(* Logix 5000 project; controller MCM_v18 1756-L63 rev 18.11; software revision 18.01 *)

TASK MainTask (continuous, watchdog 500 ms) : MainProgram

MODULES
   Local : 1756-L63 (ICP 0, rev 18.11)
      MCM : vendor 1 type 0 code 15 (ICP 1, rev 1.1, Output RPI 5 ms)   // ProSoft Technology Modbus communication module for the Control logix platform
END_MODULES

TYPE MCMBlkStat :   // This object is used to store the block transfer statistics for the module.
STRUCT
   Read : INT;   // Total number of read block transfers
   Write : INT;   // Total number of write block transfers
   Parse : INT;   // Total number of blocks parsed
   Event : INT;   // Total number of event blocks received
   Cmd : INT;   // Total number of command blocks received
   Err : INT;   // Total number of block transfer errors
END_STRUCT
END_TYPE

TYPE MCMClockType :   // Allows read/write of clock value between the module and processor
STRUCT
   Read : BOOL;   // Reads current time from the module
   Write : BOOL;   // Writes current time from the module
   Config : MCMDateTime;   // Date and time configuration read or written between the module and processor
END_STRUCT
END_TYPE

TYPE MCMCmd :   // This object is used to contain the attributes to define a master command. An array of these objects is used for each port.
STRUCT
   Enable : INT;   // 0=Disable,1=Continuous,2=Event Command
   IntAddress : INT;   // Module's internal address associated with the command
   PollInt : INT;   // Minimum number of seconds between issuance of command (0-65535 Sec)
   Count : INT;   // Number of registers associated with the command
   Swap : INT;   // Swap code used with command
   Node : INT;   // Node address of the target device on the network
   Func : INT;   // Function code for the command
   DevAddress : INT;   // Address in device associated with the command
END_STRUCT
END_TYPE

TYPE MCMCmdControl :   // Command Control
STRUCT
   TriggerCmdCntrl : BOOL;   // Trigger command control. User application will activate this trigger
   NumberOfCommands : INT;   // Number of commands per block (1 to 6)
   PortNumber : INT;   // MVI56-MCM Port Number of master port (1 or 2)
   CommandIndex : INT[6];   // Stores the command indexes for command control
   CmdsAddedToQueue : INT;   // Number of commands added to queue
   CmdControlBlockID : INT;   // Temporary variable to calculate control block ID
   CmdCntrlPending : BOOL;   // Auxiliary control command - prevents a second request before acknowledgment is received
END_STRUCT
END_TYPE

TYPE MCMCONFIG :   // This object contains the data types that apply to the configuration of the module.
STRUCT
   ModDef : MCMModule;   // Module Defintion
   Port1 : MCMPort;   // Port 1 configuration settings
   Port2 : MCMPort;   // Port 2 configuration settings
   Port1MasterCmd : MCMCmd[325];   // Master commands for Port 1 (ignore if port is configured for slave mode)
   Port2MasterCmd : MCMCmd[325];   // Master commands for Port 2 (ignore if port is configured for slave mode)
END_STRUCT
END_TYPE

TYPE MCMCONTROL :   // Stores control registers used by the processor to request special tasks from the module.
STRUCT
   WarmBoot : BOOL;   // Warm Boot
   ColdBoot : BOOL;   // Cold Boot
   SlaveControl : MCMSlaveControl;
   CmdControl : MCMCmdControl;   // Allows for a disabled command to be sent to a device (MASTER)
   EventCmd : MCMEventCmd;   // Allows a command defined in ladder to be sent to a device (MASTER)
   SlavePollStat : MCMSlavePollStatus;   // Request slave poll status for the port (MASTER).
   Passthru : MCMPassthru;   // Contains PassThru objects required when PortX.Type is set to a value between 2-4.
END_STRUCT
END_TYPE

TYPE MCMDATA :   // Contains Read Data (data read from the module to the processor) and Write Data (data written from the processor to the module)
STRUCT
   ReadData : INT[600];   // Data read from the module to the processor
   WriteData : INT[600];   // Data written from the processor to the module
END_STRUCT
END_TYPE

TYPE MCMDateTime :   // Stores the date and time value
STRUCT
   Year : DINT;
   Month : DINT;
   Day : DINT;
   Hour : DINT;
   Minute : DINT;
   Seconds : DINT;
END_STRUCT
END_TYPE

TYPE MCMEthernet :   // Stores the MVI56-MCM IP settings
STRUCT
   IP : INT[4];
   Netmask : INT[4];
   Gateway : INT[4];
END_STRUCT
END_TYPE

TYPE MCMEthernetType :   // Allows read/write Ethernet settings between the module and processor
STRUCT
   Read : BOOL;   // Enable Ethernet configuration transfer from module to processor
   Write : BOOL;   // Enable Ethernet configuration transfer from processor to module
   Config : MCMEthernet;
END_STRUCT
END_TYPE

TYPE MCMEventCmd :   // This object holds event command statistics.
STRUCT
   EventCmdTrigger : BOOL;   // Trigger for event command. User ladder must set this bit to initiate event command
   EventCmdPending : BOOL;   // Set after the ladder has sent an event cmd to the module and is waiting for the status to be returned
   PortNumber : INT;   // Module master port number associated to this request (1 or 2)
   SlaveAddress : INT;   // Slave target modbus address
   InternalDBAddress : INT;   // Internal database address
   PointCount : INT;   // Number of points for this command
   SwapCode : INT;   // Swap code (0= no swap, 1=swap words, 2=swap words and bytes, 3=swap bytes)
   ModbusFunctionCode : INT;   // Modbus function code
   DeviceDBAddress : INT;   // Modbus register address in target modbus slave
   EventCmdStatusReturned : INT;   // (0=Fail, 1=Sucess)
   EventBlockID : INT;   // Temporary variable to calculate event block ID
END_STRUCT
END_TYPE

TYPE MCMModule :   // This object contains the information used to define the data movement between the module and the processor.
STRUCT
   WriteStartReg : INT;   // Start reg to transfer from PLC to module
   WriteRegCnt : INT;   // Number of registers to write from PLC
   ReadStartReg : INT;   // Start reg to transfer from module to PLC
   ReadRegCnt : INT;   // Number of registers to transfer from module
   BPFail : INT;   // Determines module operation if BP fails 0=continue,>0=number of retries before comm shutdown
   ErrStatPtr : INT;   // Internal DB start register for status data (-1=Ignore)
END_STRUCT
END_TYPE

TYPE MCMModuleDef :   // This object contains the data types that apply to the operation of the module.
STRUCT
   CONFIG : MCMCONFIG;   // Module and port configuration
   DATA : MCMDATA;   // Modbus data transferred between module and processor
   STATUS : MCMSTATUS;   // Status information in each read block
   CONTROL : MCMCONTROL;   // Optional requests from the processor to the module
   UTIL : MCMUTIL;   // Variables for internal ladder usage - should not be accessed by user application
END_STRUCT
END_TYPE

TYPE MCMPassthru :   // Used to send pass-through data between the processor and the Modbus devices connected to the MVI56-MCM module.
STRUCT
   MBControl1 : CONTROL;   // Used for data to be passed through to the processor
   MBControl2 : CONTROL;   // Used for data to be passed through to the processor
   Mbdouble : DINT;   // Modbus double int tag
   MBMsg : SINT[500];   // Modbus Message
   MBMsgLen : INT;   // Modbus Offset Length
   MBOffset : INT;   // Modbus Offset
   MBOffsetBit : INT;   // Modbus Offset Bit
   MBScratch : INT[3];   // Modbus Scratch
   MBboollength : DINT;   // Holds Word size that will accommodate Coil Qty.
   MBSpecial : INT[4];   // Holds Special Function 99 data.
END_STRUCT
END_TYPE

TYPE MCMPort :   // The serial port configuration for the MVI56MCM module.
STRUCT
   Enabled : INT;   // O=Port Disabled,1=Port Enabled
   Type : INT;   // 0=Master, 1=Slave, 2=Slave: pass-through, 3=Slave: formatted pass-through/data swapped, 4=Slave: form. pass-through
   FloatFlag : INT;   // 0=No floating-point data, 1=Use floating-point data
   FloatStart : INT;   // Register offset in message for floating-point data
   FloatOffset : INT;   // Internal DB offset to start of floating-point data
   Protocol : INT;   // 0=Modbus RTU, 1=Modbus ASCII
   Baudrate : INT;   // Baudrate for port (110 to 115.2K)
   Parity : INT;   // 0=None, 1=Odd, 2=Even, 3=Mark, 4=Space
   DataBits : INT;   // 5 to 8 data bits
   StopBits : INT;   // 1 or 2 stop bits
   RTSOn : INT;   // 0-65535 mSec delay before data
   RTSOff : INT;   // 0-65535 mSec delay after data
   MinResp : INT;   // 0-65535 mSec minimum time before response to request
   UseCTS : INT;   // 0=No, 1=Yes to use CTS modem line
   SlaveID : INT;   // 1-255 Modbus Node Address (Slave)
   BitInOffset : INT;   // Internal DB offset to bit input data (Slave)
   WordInOffset : INT;   // Internal DB offset to word input data (Slave)
   OutOffset : INT;   // Internal DB offset to bit output data (Slave)
   HoldOffset : INT;   // Internal DB offset to holding register data (Slave)
   CmdCount : INT;   // Command list count (Master)
   MinCmdDelay : INT;   // 0-65535 mSec minimum time between each command (Master)
   CmdErrPtr : INT;   // Internal DB location to place command error list (Master)
   RespTO : INT;   // 0-65535 mSec response timeout for command (Master)
   RetryCount : INT;   // Retry count for failed request (Master)
   ErrorDelayCntr : INT;   // 0-65535 Command cycle count if error (Master)
   Reserved : INT;   // Reserved (Previously was UseGuardBand parameter)
   InterCharacterDelay : INT;   // 0-65535 mSec time between characters to signal end of message
   Fcn99Offset : INT;   // Internal DB offset to function 99 counter
END_STRUCT
END_TYPE

TYPE MCMPortErrors :   // This object is used to store the port statistics for an MVI56-MCM port.
STRUCT
   CmdReq : INT;   // Total number of command list requests sent
   CmdResp : INT;   // Total number of command list responses received
   CmdErr : INT;   // Total number of command list errors
   Requests : INT;   // Total number of requests for port
   Responses : INT;   // Total number of responses for port
   ErrSent : INT;   // Total number of errors sent
   ErrRec : INT;   // Total number of errors received
END_STRUCT
END_TYPE

TYPE MCMSlaveControl :   // Special block processing for Slave Control.
STRUCT
   TriggerSlaveControl : BOOL;   // Trigger to Enable or Disable Slaves
   PortNumber : INT;   // Slave Address
   NumberOfSlaves : INT;   // Number of Slaves
   BlockNumber : INT;   // Block ID number
   SlaveIndexes : INT[200];   // Slave Indexes
   NumberOfSlavesProcessed : INT;   // Number of Slaves processed
   EnableSlaves : BOOL;   // Set 0 to Disable or 1 to Enable Slaves
END_STRUCT
END_TYPE

TYPE MCMSlavePollStatus :   // This object contains all of the Slave Polling status (used when the port is used as a master)
STRUCT
   Port1Slave0Read : BOOL;   // Port 1 read slave polling status. (range 0-127)
   Port1Slave128Read : BOOL;   // Port 1 read slave polling status. (range 128-255)
   Port2Slave0Read : BOOL;   // Port 2 read slave polling status. (range 0-127)
   Port2Slave128Read : BOOL;   // Port 2 read slave polling status. (range 128-255)
   P1Slaves : INT[256];   // P1 Slave Status
   P2Slaves : INT[256];   // P2 Slave Status
END_STRUCT
END_TYPE

TYPE MCMSTATUS :   // This status data is returned on each read block and can be used to detect proper module operation.
STRUCT
   PassCnt : INT;   // Program cycle counter
   Product : INT[2];   // Product Name
   Rev : INT[2];   // Revision Level Number
   OP : INT[2];   // Operating Level Number
   Run : INT[2];   // Run Number
   Prt1Errs : MCMPortErrors;   // Port 1 error statistics
   Prt2Errs : MCMPortErrors;   // Port 2 error statistics
   Blk : MCMBlkStat;   // Block transfer statistics
   Port1LastErr : INT;   // Last command index that received an error on Port 1
   Port1PreviousErr : INT;   // Previous Command index that received an error on Port 1
   Port2LastErr : INT;   // Last command index that received an error on Port 2
   Port2PreviousErr : INT;   // Previous Command index that received an error on Port 2
END_STRUCT
END_TYPE

TYPE MCMUTIL :   // Stores tags that are used by the ladder logic for internal processing.
STRUCT
   BPLastRead : INT;   // Index of last read block
   BPLastWrite : INT;   // Index of last write block
   BlockIndex : INT;   // Computed block offset for data table
   ReadDataSize : DINT;   // Size of Read Data Array
   MaxReadBlock : DINT;   // Maximum read block
   WriteDataSize : DINT;   // Size of Write Data Array
   MaxWriteBlock : DINT;   // Maximum write block
   RBTSremainder : INT;   // Contains remainder from Read Data array size divided by the block size
   WBTSremainder : INT;   // Contains remainder from Write Data array size divided by the block size
END_STRUCT
END_TYPE

ADD_ON_INSTRUCTION AOI56EMCM_Optional   (* revision 1.2, vendor ProSoft Technology Inc. *)
// MVI56E-MCM Optional Add-On Ethernet/Clock.
// Revision note:
// v1.2 - Updated name and description for standardization. No feature changes.
VAR_IN_OUT
   MVI56MCMEthernet : MCMEthernetType; {required}   // MVI56E-MCM Rev2 Ethernet Settings
   MVI56MCMClock : MCMClockType; {required}   // MVI56E-MCM Rev2 Clock Settings
   ReadEthernetMSG : MESSAGE; {required}   // Read Ethernet Settings Message
   WriteEthernetMSG : MESSAGE; {required}   // Write Ethernet Settings Message
   ReadClockMSG : MESSAGE; {required}   // Read Clock Settings Message
   WriteClockMSG : MESSAGE; {required}   // Write Clock Settings Message
END_VAR

ROUTINE Logic   (* ladder *)
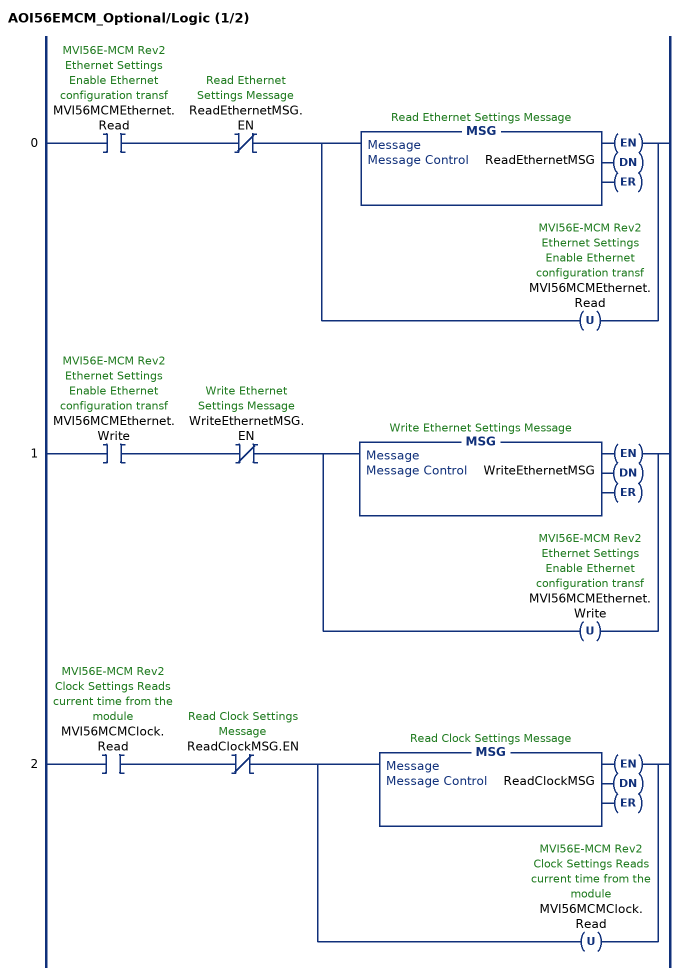
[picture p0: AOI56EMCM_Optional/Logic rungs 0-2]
   0: XIC(MVI56MCMEthernet.Read)XIO(ReadEthernetMSG.EN)[MSG(ReadEthernetMSG) ,OTU(MVI56MCMEthernet.Read) ];
   1: XIC(MVI56MCMEthernet.Write)XIO(WriteEthernetMSG.EN)[MSG(WriteEthernetMSG) ,OTU(MVI56MCMEthernet.Write) ];
   2: XIC(MVI56MCMClock.Read)XIO(ReadClockMSG.EN)[MSG(ReadClockMSG) ,OTU(MVI56MCMClock.Read) ];
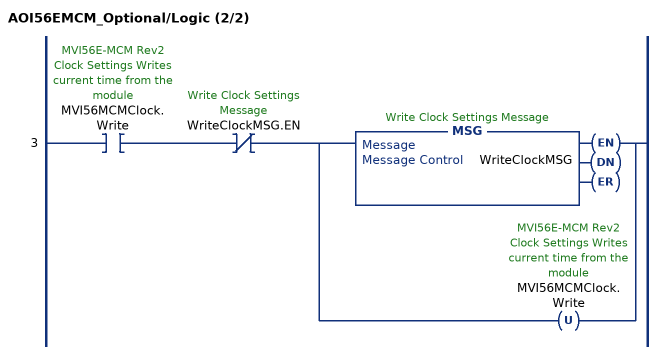
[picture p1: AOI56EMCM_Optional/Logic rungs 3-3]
   3: XIC(MVI56MCMClock.Write)XIO(WriteClockMSG.EN)[MSG(WriteClockMSG) ,OTU(MVI56MCMClock.Write) ];
END_ROUTINE
END_ADD_ON_INSTRUCTION

ADD_ON_INSTRUCTION AOI56MCM   (* revision 2.8, vendor ProSoft Technology Inc., ExecutePrescan *)
// This Add-On supports MVI56E-MCM modules version 3.01 and newer.
// Revision note:
// v2.8 - changes to the amount commands, now each port can support up to 325 commands.
VAR_IN_OUT
   Connection_Input : INT[250]; {required}
   Connection_Output : INT[248]; {required}
   MCM : MCMModuleDef; {required}
END_VAR
VAR
   MJFAULTS : DINT[12];
END_VAR

ROUTINE Logic   (* ladder *)
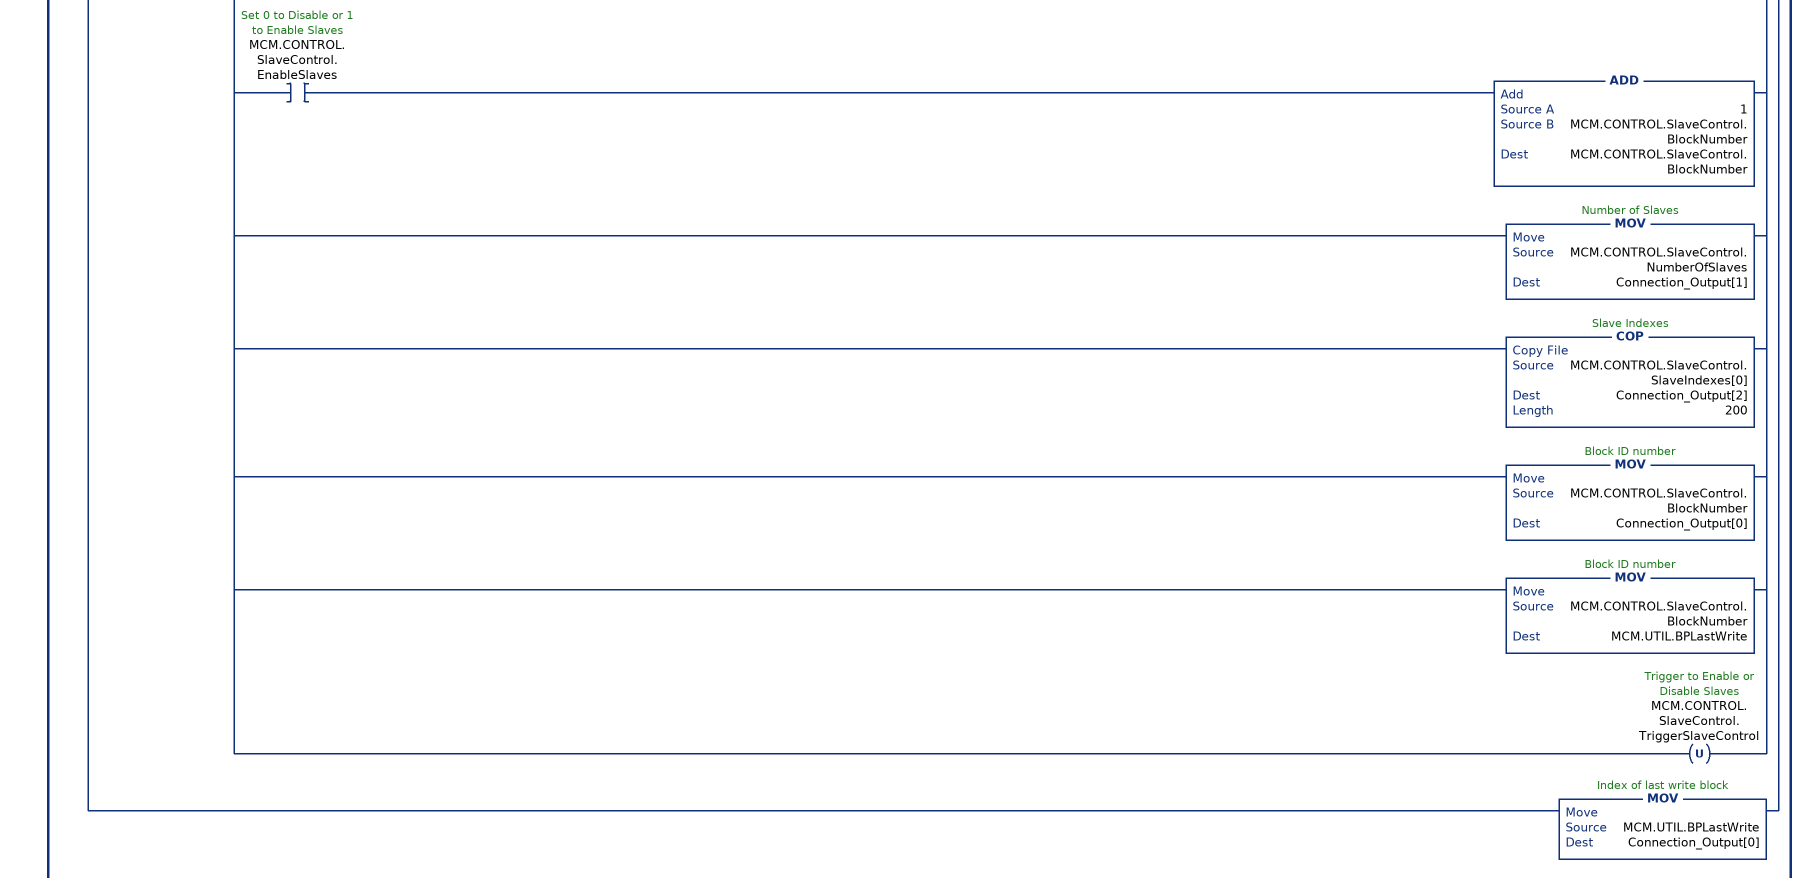
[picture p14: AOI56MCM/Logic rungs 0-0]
   0: NEQ(Connection_Input[249],MCM.UTIL.BPLastRead)[MOV(Connection_Input[249],MCM.UTIL.BPLastRead) ,[EQU(-1,MCM.UTIL.BPLastRead) ,EQU(0,MCM.UTIL.BPLastRead) ] [COP(Connection_Input[202],MCM.STATUS.PassCnt,1) ,COP(Connection_Input[203],MCM.STATUS.Product[0],8) ,COP(Connection_Input[211],MCM.STATUS.Prt1Errs.CmdReq,7) ,COP(Connection_Input[218],MCM.STATUS.Prt2Errs.CmdReq,7) ,COP(Connection_Input[225],MCM.STATUS.Blk.Read,6) ,COP(Connection_Input[231],MCM.STATUS.Port1LastErr,4) ] ,[GEQ(MCM.UTIL.BPLastRead,1) [LEQ(MCM.UTIL.BPLastRead,MCM.UTIL.MaxReadBlock) [CPT(MCM.UTIL.BlockIndex,(MCM.UTIL.BPLastRead - 1) * 200) ,COP(Connection_Input[2],MCM.DATA.ReadData[MCM.UTIL.BlockIndex],200) ] ,CMP(MCM.UTIL.BPLastRead - MCM.UTIL.MaxReadBlock = 1) GRT(MCM.UTIL.RBTSremainder,0) [CPT(MCM.UTIL.BlockIndex,(MCM.UTIL.BPLastRead - 1) * 200) ,COP(Connection_Input[2],MCM.DATA.ReadData[MCM.UTIL.BlockIndex],MCM.UTIL.RBTSremainder) ] ] ,COP(Connection_Input[202],MCM.STATUS.PassCnt,1) ,COP(Connection_Input[203],MCM.STATUS.Product[0],8) ,COP(Connection_Input[211],MCM.STATUS.Prt1Errs.CmdReq,7) ,COP(Connection_Input[218],MCM.STATUS.Prt2Errs.CmdReq,7) ,COP(Connection_Input[225],MCM.STATUS.Blk.Read,6) ,COP(Connection_Input[231],MCM.STATUS.Port1LastErr,4) ] ,EQU(9996,MCM.UTIL.BPLastRead) [MOV(Connection_Input[2],MCM.CONTROL.Passthru.MBMsgLen) ,COP(Connection_Input[4],MCM.CONTROL.Passthru.MBMsg[0],MCM.CONTROL.Passthru.MBMsgLen) ] ,LIM(9956,MCM.UTIL.BPLastRead,9957) [MOV(Connection_Input[3],MCM.CONTROL.Passthru.MBOffset) ,LES(MCM.CONTROL.Passthru.MBOffset,MCM.UTIL.WriteDataSize) COP(Connection_Input[4],MCM.DATA.WriteData[MCM.CONTROL.Passthru.MBOffset],Connection_Input[2]) ] ,EQU(9958,MCM.UTIL.BPLastRead) [MOV(Connection_Input[3],MCM.CONTROL.PassThru.MBOffsetBit) ,MOV(Connection_Input[4],MCM.CONTROL.PassThru.MBScratch[2]) ,DIV(MCM.CONTROL.PassThru.MBOffsetBit,16,MCM.CONTROL.PassThru.MBOffset) ,MOD(MCM.CONTROL.PassThru.MBOffsetBit,16,MCM.CONTROL.PassThru.MBOffsetBit) ,XPY(2,MCM.CONTROL.PassThru.MBOffsetBit,MCM.CONTROL.PassThru.mbdouble) ,MVM(MCM.CONTROL.PassThru.mbdouble,16#0000_ffff,MCM.CONTROL.PassThru.MBOffsetBit) ,GEQ(MCM.CONTROL.PassThru.MBOffset,0) LES(MCM.CONTROL.PassThru.MBOffset,MCM.UTIL.WriteDataSize) LEQ(MCM.CONTROL.PassThru.MBOffset,2048) [NEQ(MCM.CONTROL.PassThru.MBScratch[2],0) OR(MCM.CONTROL.PassThru.MBOffsetBit,MCM.DATA.WriteData[MCM.CONTROL.PassThru.MBOffset],MCM.DATA.WriteData[MCM.CONTROL.PassThru.MBOffset]) ,EQU(MCM.CONTROL.PassThru.MBScratch[2],0) [NOT(MCM.CONTROL.PassThru.MBOffsetBit,MCM.CONTROL.PassThru.MBOffsetBit) ,AND(MCM.CONTROL.PassThru.MBOffsetBit,MCM.DATA.WriteData[MCM.CONTROL.PassThru.MBOffset],MCM.DATA.WriteData[MCM.CONTROL.PassThru.MBOffset]) ] ] ] ,EQU(9959,MCM.UTIL.BPLastRead) [MOV(Connection_Input[3],MCM.CONTROL.Passthru.MBOffset) ,MOV(Connection_Input[2],MCM.CONTROL.Passthru.MBControl1.LEN) ,MOV(Connection_Input[2],MCM.CONTROL.Passthru.MBControl2.LEN) ,FAL(MCM.CONTROL.Passthru.MBControl1,?,?,ALL,MCM.DATA.WriteData[MCM.CONTROL.Passthru.MBOffset+MCM.CONTROL.Passthru.MBControl1.POS],MCM.DATA.WriteData[MCM.CONTROL.Passthru.MBOffset+MCM.CONTROL.Passthru.MBControl1.POS] AND(NOT Connection_Input[54+MCM.CONTROL.Passthru.MBControl1.POS])) ,FAL(MCM.CONTROL.Passthru.MBControl2,?,?,ALL,MCM.DATA.WriteData[MCM.CONTROL.Passthru.MBOffset+MCM.CONTROL.Passthru.MBControl2.POS],MCM.DATA.WriteData[MCM.CONTROL.Passthru.MBOffset+MCM.CONTROL.Passthru.MBControl2.POS] OR(Connection_Input[54+MCM.CONTROL.Passthru.MBControl2.POS] AND Connection_Input[4+MCM.CONTROL.Passthru.MBControl2.POS])) ,RES(MCM.CONTROL.Passthru.MBControl1) ,RES(MCM.CONTROL.Passthru.MBControl2) ] ,LIM(3002,MCM.UTIL.BPLastRead,3003) [CPT(MCM.UTIL.BlockIndex,(MCM.UTIL.BPLastRead-3002)*128) ,COP(Connection_Input[2],MCM.CONTROL.SlavePollStat.P1Slaves[MCM.UTIL.BlockIndex],128) ] ,LIM(3102,MCM.UTIL.BPLastRead,3103) [CPT(MCM.UTIL.BlockIndex,(MCM.UTIL.BPLastRead-3102)*128) ,COP(Connection_Input[2],MCM.CONTROL.SlavePollStat.P2Slaves[MCM.UTIL.BlockIndex],128) ] ,[LIM(5001,MCM.UTIL.BPLastRead,5006) ,LIM(5101,MCM.UTIL.BPLastRead,5106) ] [MOV(Connection_Input[2],MCM.CONTROL.CmdControl.CmdsAddedToQueue) ,OTU(MCM.CONTROL.CmdControl.CmdCntrlPending) ,OTU(MCM.CONTROL.CmdControl.TriggerCmdCntrl) ] ,[LIM(1000,MCM.UTIL.BPLastRead,1255) ,LIM(2000,MCM.UTIL.BPLastRead,2255) ] [MOV(Connection_Input[2],MCM.CONTROL.EventCmd.EventCmdStatusReturned) ,OTU(MCM.CONTROL.EventCmd.EventCmdPending) ,OTU(MCM.CONTROL.EventCmd.EventCmdTrigger) ] ,EQU(-9000,MCM.UTIL.BPLastRead) [COP(Connection_Input[2],MCM.CONFIG.ModDef.WriteStartReg,6) ,COP(Connection_Input[8],MCM.CONFIG.Port1.Enabled,25) ,COP(Connection_Input[33],MCM.CONFIG.Port2.Enabled,25) ,COP(Connection_Input[58],MCM.CONFIG.Port1.Reserved,3) ,COP(Connection_Input[61],MCM.CONFIG.Port2.Reserved,3) ,MOV(MCM.UTIL.BPLastRead,Connection_Output[0]) ] ,LIM(-6012,MCM.UTIL.BPLastRead,-6000) [CPT(MCM.UTIL.BPLastWrite,(-MCM.UTIL.BPLastRead-6000)*25) ,COP(Connection_Input[2],MCM.CONFIG.Port1MasterCmd[MCM.UTIL.BPLastWrite].Enable,200) ,MOV(MCM.UTIL.BPLastRead,Connection_Output[0]) ] ,LIM(-6112,MCM.UTIL.BPLastRead,-6100) [CPT(MCM.UTIL.BPLastWrite,(-MCM.UTIL.BPLastRead-6100)*25) ,COP(Connection_Input[2],MCM.CONFIG.Port2MasterCmd[MCM.UTIL.BPLastWrite].Enable,200) ,MOV(MCM.UTIL.BPLastRead,Connection_Output[0]) ] ,MOV(Connection_Input[1],MCM.UTIL.BPLastWrite) ,XIC(MCM.CONTROL.WarmBoot) [MOV(9998,MCM.UTIL.BPLastWrite) ,OTU(MCM.CONTROL.WarmBoot) ] ,XIC(MCM.CONTROL.ColdBoot) [MOV(9999,MCM.UTIL.BPLastWrite) ,OTU(MCM.CONTROL.ColdBoot) ] ,GEQ(MCM.UTIL.BPLastWrite,1) [LEQ(MCM.UTIL.BPLastWrite,MCM.UTIL.MaxWriteBlock) [CPT(MCM.UTIL.BlockIndex,(MCM.UTIL.BPLastWrite - 1) * 200) ,COP(MCM.DATA.WriteData[MCM.UTIL.BlockIndex],Connection_Output[1],200) ] ,CMP(MCM.UTIL.BPLastWrite - MCM.UTIL.MaxWriteBlock = 1) GRT(MCM.UTIL.WBTSremainder,0) [CPT(MCM.UTIL.BlockIndex,(MCM.UTIL.BPLastWrite - 1) * 200) ,COP(MCM.DATA.WriteData[MCM.UTIL.BlockIndex],Connection_Output[1],MCM.UTIL.WBTSremainder) ] ] ,EQU(9000,MCM.UTIL.BPLastWrite) [COP(MCM.CONFIG.ModDef.WriteStartReg,Connection_Output[1],6) ,COP(MCM.CONFIG.Port1.Enabled,Connection_Output[7],25) ,COP(MCM.CONFIG.Port2.Enabled,Connection_Output[32],25) ,COP(MCM.CONFIG.Port1.Reserved,Connection_Output[57],3) ,COP(MCM.CONFIG.Port2.Reserved,Connection_Output[60],3) ] ,LIM(6000,MCM.UTIL.BPLastWrite,6012) [CPT(MCM.UTIL.BlockIndex,(MCM.UTIL.BPLastWrite-6000)*25) ,COP(MCM.CONFIG.Port1MasterCmd[MCM.UTIL.BlockIndex].Enable,Connection_Output[1],200) ] ,LIM(6100,MCM.UTIL.BPLastWrite,6112) [CPT(MCM.UTIL.BlockIndex,(MCM.UTIL.BPLastWrite-6100)*25) ,COP(MCM.CONFIG.Port2MasterCmd[MCM.UTIL.BlockIndex].Enable,Connection_Output[1],200) ] ,XIC(MCM.CONTROL.SlavePollStat.Port1Slave0Read) [MOV(3002,MCM.UTIL.BPLastWrite) ,OTU(MCM.CONTROL.SlavePollStat.Port1Slave0Read) ] ,XIC(MCM.CONTROL.SlavePollStat.Port1Slave128Read) [MOV(3003,MCM.UTIL.BPLastWrite) ,OTU(MCM.CONTROL.SlavePollStat.Port1Slave128Read) ] ,XIC(MCM.CONTROL.SlavePollStat.Port2Slave0Read) [MOV(3102,MCM.UTIL.BPLastWrite) ,OTU(MCM.CONTROL.SlavePollStat.Port2Slave0Read) ] ,XIC(MCM.CONTROL.SlavePollStat.Port2Slave128Read) [MOV(3103,MCM.UTIL.BPLastWrite) ,OTU(MCM.CONTROL.SlavePollStat.Port2Slave128Read) ] ,XIC(MCM.CONTROL.CmdControl.TriggerCmdCntrl) XIO(MCM.CONTROL.CmdControl.CmdCntrlPending) [COP(MCM.CONTROL.CmdControl.CommandIndex[0],Connection_Output[1],6) ,ADD(5000,MCM.CONTROL.CmdControl.NumberOfCommands,MCM.CONTROL.CmdControl.CmdControlBlockID) ,EQU(MCM.CONTROL.CmdControl.PortNumber,2) ADD(100,MCM.CONTROL.CmdControl.CmdControlBlockID,MCM.CONTROL.CmdControl.CmdControlBlockID) ,MOV(MCM.CONTROL.CmdControl.CmdControlBlockID,MCM.UTIL.BPLastWrite) ,OTL(MCM.CONTROL.CmdControl.CmdCntrlPending) ] ,XIC(MCM.CONTROL.EventCmd.EventCmdTrigger) XIO(MCM.CONTROL.EventCmd.EventCmdPending) [COP(MCM.CONTROL.EventCmd.InternalDBAddress,Connection_Output[1],5) ,ADD(1000,MCM.CONTROL.EventCmd.SlaveAddress,MCM.CONTROL.EventCmd.EventBlockID) ,EQU(MCM.CONTROL.EventCmd.PortNumber,2) ADD(MCM.CONTROL.EventCmd.EventBlockID,1000,MCM.CONTROL.EventCmd.EventBlockID) ,MOV(MCM.CONTROL.EventCmd.EventBlockID,MCM.UTIL.BPLastWrite) ,OTL(MCM.CONTROL.EventCmd.EventCmdPending) ] ,[LIM(3000,Connection_Input[249],3001) ,LIM(3100,Connection_Input[249],3101) ] MOV(Connection_Input[2],MCM.CONTROL.SlaveControl.NumberOfSlavesProcessed) ,XIC(MCM.CONTROL.SlaveControl.TriggerSlaveControl) [MOV(3000,MCM.CONTROL.SlaveControl.BlockNumber) ,EQU(MCM.CONTROL.SlaveControl.PortNumber,2) ADD(100,MCM.CONTROL.SlaveControl.BlockNumber,MCM.CONTROL.SlaveControl.BlockNumber) ,XIC(MCM.CONTROL.SlaveControl.EnableSlaves) ADD(1,MCM.CONTROL.SlaveControl.BlockNumber,MCM.CONTROL.SlaveControl.BlockNumber) ,MOV(MCM.CONTROL.SlaveControl.NumberOfSlaves,Connection_Output[1]) ,COP(MCM.CONTROL.SlaveControl.SlaveIndexes[0],Connection_Output[2],200) ,MOV(MCM.CONTROL.SlaveControl.BlockNumber,Connection_Output[0]) ,MOV(MCM.CONTROL.SlaveControl.BlockNumber,MCM.UTIL.BPLastWrite) ,OTU(MCM.CONTROL.SlaveControl.TriggerSlaveControl) ] ,MOV(MCM.UTIL.BPLastWrite,Connection_Output[0]) ];
END_ROUTINE

ROUTINE Prescan   (* ladder *)
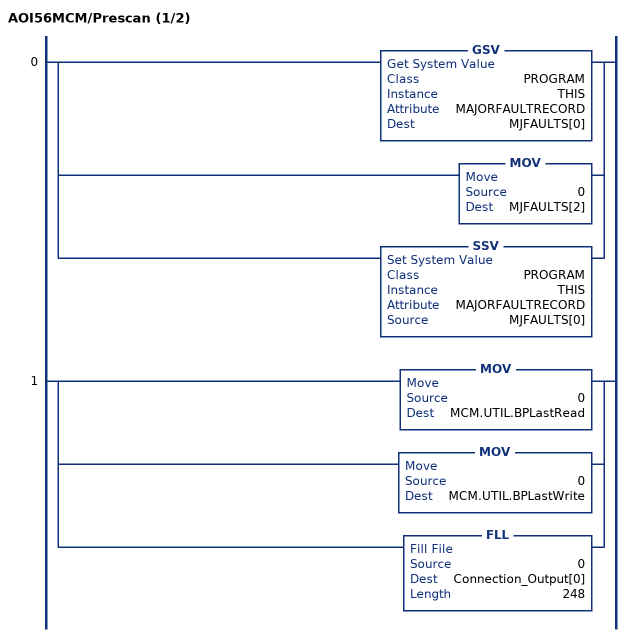
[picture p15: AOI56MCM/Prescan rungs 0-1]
   0: [GSV(PROGRAM,THIS,MAJORFAULTRECORD,MJFAULTS[0]) ,MOV(0,MJFAULTS[2]) ,SSV(PROGRAM,THIS,MAJORFAULTRECORD,MJFAULTS[0]) ];
   1: [MOV(0,MCM.UTIL.BPLastRead) ,MOV(0,MCM.UTIL.BPLastWrite) ,FLL(0,Connection_Output[0],248) ];
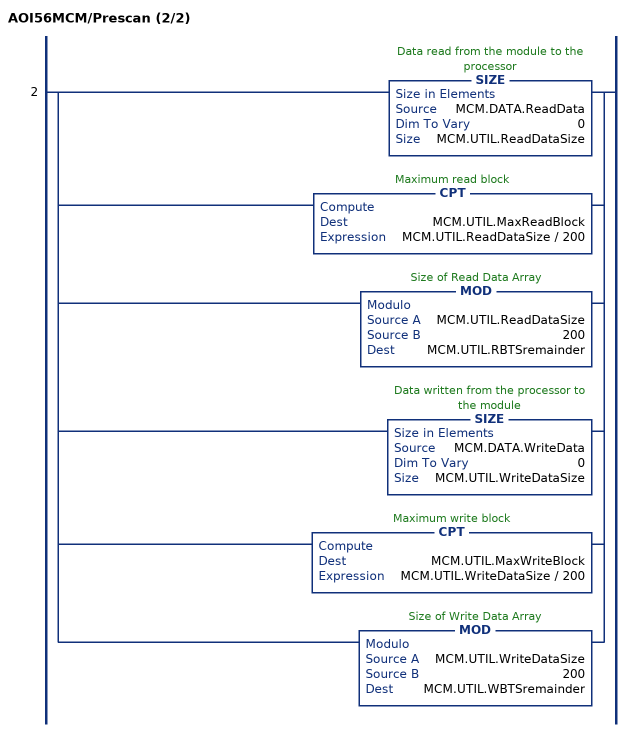
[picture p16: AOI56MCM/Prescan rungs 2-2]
   2: [SIZE(MCM.DATA.ReadData,0,MCM.UTIL.ReadDataSize) ,CPT(MCM.UTIL.MaxReadBlock,MCM.UTIL.ReadDataSize / 200) ,MOD(MCM.UTIL.ReadDataSize,200,MCM.UTIL.RBTSremainder) ,SIZE(MCM.DATA.WriteData,0,MCM.UTIL.WriteDataSize) ,CPT(MCM.UTIL.MaxWriteBlock,MCM.UTIL.WriteDataSize / 200) ,MOD(MCM.UTIL.WriteDataSize,200,MCM.UTIL.WBTSremainder) ];
END_ROUTINE
END_ADD_ON_INSTRUCTION

VAR_GLOBAL   (* controller tags *)
   AOI56EMCM_Optional : AOI56EMCM_Optional;
   AOI56MCM : AOI56MCM;
   MCM : MCMModuleDef;
   MVI56EMCMClock : MCMClockType;
   MVI56EMCMEthernet : MCMEthernetType;
   ReadClockMSG : MESSAGE;
        MessageParameters(ServiceCode := 16#000e, DestinationTag := MVI56EMCMClock.Config, ...)
   ReadEthernetMSG : MESSAGE;
        MessageParameters(ServiceCode := 16#000e, DestinationTag := MVI56EMCMEthernet.Config, ...)
   WriteClockMSG : MESSAGE;
        MessageParameters(ServiceCode := 16#0010, LocalElement := MVI56EMCMClock.Config, ...)
   WriteEthernetMSG : MESSAGE;
        MessageParameters(ServiceCode := 16#0010, LocalElement := MVI56EMCMEthernet.Config, ...)
END_VAR

PROGRAM MainProgram   (* main routine MainRoutine *)

ROUTINE MainRoutine   (* ladder *)
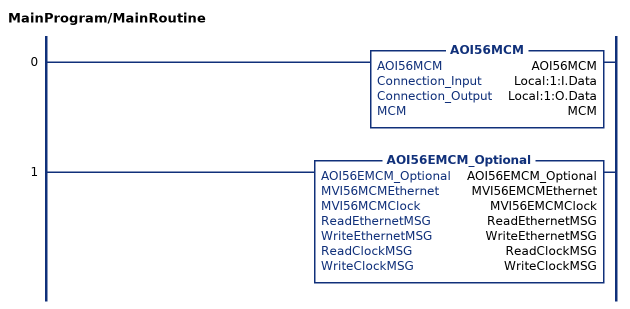
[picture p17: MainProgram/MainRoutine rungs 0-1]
   0: AOI56MCM(AOI56MCM,Local:1:I.Data,Local:1:O.Data,MCM);
   1: AOI56EMCM_Optional(AOI56EMCM_Optional,MVI56EMCMEthernet,MVI56EMCMClock,ReadEthernetMSG,WriteEthernetMSG,ReadClockMSG,WriteClockMSG);
END_ROUTINE
END_PROGRAM
